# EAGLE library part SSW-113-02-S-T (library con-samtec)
THROUGH-HOLE .025" SQ POST SOCKET Source: Samtec SSW.pdf
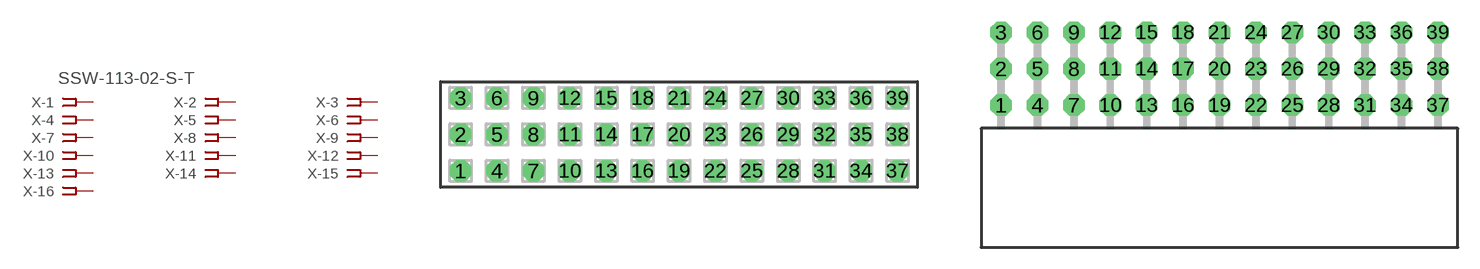
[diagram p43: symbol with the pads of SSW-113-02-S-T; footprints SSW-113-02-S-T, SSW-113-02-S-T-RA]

Designator prefix X; gates -1=FPINV -2=FPIN -3=FPIN -4=FPIN -5=FPIN -6=FPIN -7=FPIN -8=FPIN -9=FPIN -10=FPIN -11=FPIN -12=FPIN -13=FPIN -14=FPIN -15=FPIN -16=FPIN -17=FPIN -18=FPIN -19=FPIN -20=FPIN -21=FPIN -22=FPIN -23=FPIN -24=FPIN -25=FPIN -26=FPIN -27=FPIN -28=FPIN -29=FPIN -30=FPIN -31=FPIN -32=FPIN -33=FPIN -34=FPIN -35=FPIN -36=FPIN -37=FPIN -38=FPIN -39=FPIN

## SSW-113-02-S-T (MPN: SSW-113-02-S-T; OC_FARNELL: unknown; OC_NEWARK: 82P6269)  [SSW-113-02-S-T]
1  -1:1  pas
2  -2:1  pas
3  -3:1  pas
4  -4:1  pas
5  -5:1  pas
6  -6:1  pas
7  -7:1  pas
8  -8:1  pas
9  -9:1  pas
10  -10:1  pas
11  -11:1  pas
12  -12:1  pas
13  -13:1  pas
14  -14:1  pas
15  -15:1  pas
16  -16:1  pas
17  -17:1  pas
18  -18:1  pas
19  -19:1  pas
20  -20:1  pas
21  -21:1  pas
22  -22:1  pas
23  -23:1  pas
24  -24:1  pas
25  -25:1  pas
26  -26:1  pas
27  -27:1  pas
28  -28:1  pas
29  -29:1  pas
30  -30:1  pas
31  -31:1  pas
32  -32:1  pas
33  -33:1  pas
34  -34:1  pas
35  -35:1  pas
36  -36:1  pas
37  -37:1  pas
38  -38:1  pas
39  -39:1  pas

## SSW-113-02-S-TRA (MPN: SSW-113-02-S-T-RA; OC_FARNELL: unknown; OC_NEWARK: 82P6270)  [SSW-113-02-S-T-RA]
Pads as for SSW-113-02-S-T

## Footprint SSW-113-02-S-T (pad centres in mm)
THROUGH-HOLE .025" SQ POST SOCKET Source: Samtec SSW.pdf
drill 1 pad 1.5 octagon: 1 -15.24,-2.54; 2 -15.24,0; 3 -15.24,2.54; 4 -12.7,-2.54; 5 -12.7,0; 6 -12.7,2.54; 7 -10.16,-2.54; 8 -10.16,0; 9 -10.16,2.54; 10 -7.62,-2.54; 11 -7.62,0; 12 -7.62,2.54; 13 -5.08,-2.54; 14 -5.08,0; 15 -5.08,2.54; 16 -2.54,-2.54; 17 -2.54,0; 18 -2.54,2.54; 19 0,-2.54; 20 0,0; 21 0,2.54; 22 2.54,-2.54; 23 2.54,0; 24 2.54,2.54; 25 5.08,-2.54; 26 5.08,0; 27 5.08,2.54; 28 7.62,-2.54; 29 7.62,0; 30 7.62,2.54; 31 10.16,-2.54; 32 10.16,0; 33 10.16,2.54; 34 12.7,-2.54; 35 12.7,0; 36 12.7,2.54; 37 15.24,-2.54; 38 15.24,0; 39 15.24,2.54

## Footprint SSW-113-02-S-T-RA (pad centres in mm)
THROUGH-HOLE .025" SQ POST SOCKET Source: Samtec SSW.pdf
drill 1 pad 1.5 octagon: 1 -15.24,1.524; 2 -15.24,4.064; 3 -15.24,6.604; 4 -12.7,1.524; 5 -12.7,4.064; 6 -12.7,6.604; 7 -10.16,1.524; 8 -10.16,4.064; 9 -10.16,6.604; 10 -7.62,1.524; 11 -7.62,4.064; 12 -7.62,6.604; 13 -5.08,1.524; 14 -5.08,4.064; 15 -5.08,6.604; 16 -2.54,1.524; 17 -2.54,4.064; 18 -2.54,6.604; 19 0,1.524; 20 0,4.064; 21 0,6.604; 22 2.54,1.524; 23 2.54,4.064; 24 2.54,6.604; 25 5.08,1.524; 26 5.08,4.064; 27 5.08,6.604; 28 7.62,1.524; 29 7.62,4.064; 30 7.62,6.604; 31 10.16,1.524; 32 10.16,4.064; 33 10.16,6.604; 34 12.7,1.524; 35 12.7,4.064; 36 12.7,6.604; 37 15.24,1.524; 38 15.24,4.064; 39 15.24,6.604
